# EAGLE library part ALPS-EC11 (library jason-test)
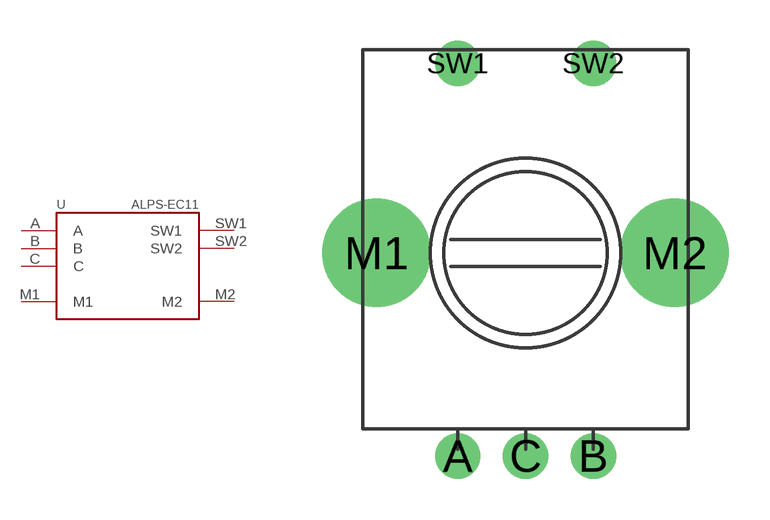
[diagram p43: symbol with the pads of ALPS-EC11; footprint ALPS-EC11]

Designator prefix -

## ALPS-EC11  [ALPS-EC11]
A  A
B  B
C  C
M1  M1
M2  M2
SW1  SW1
SW2  SW2

## Footprint ALPS-EC11 (pad centres in mm)
drill 1 pad 1.676 round: A -2.5,-7.5; B 2.5,-7.5; C 0,-7.5; SW1 -2.5,7; SW2 2.5,7
drill 2.6 pad 4 round: M1 -5.5,0; M2 5.5,0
